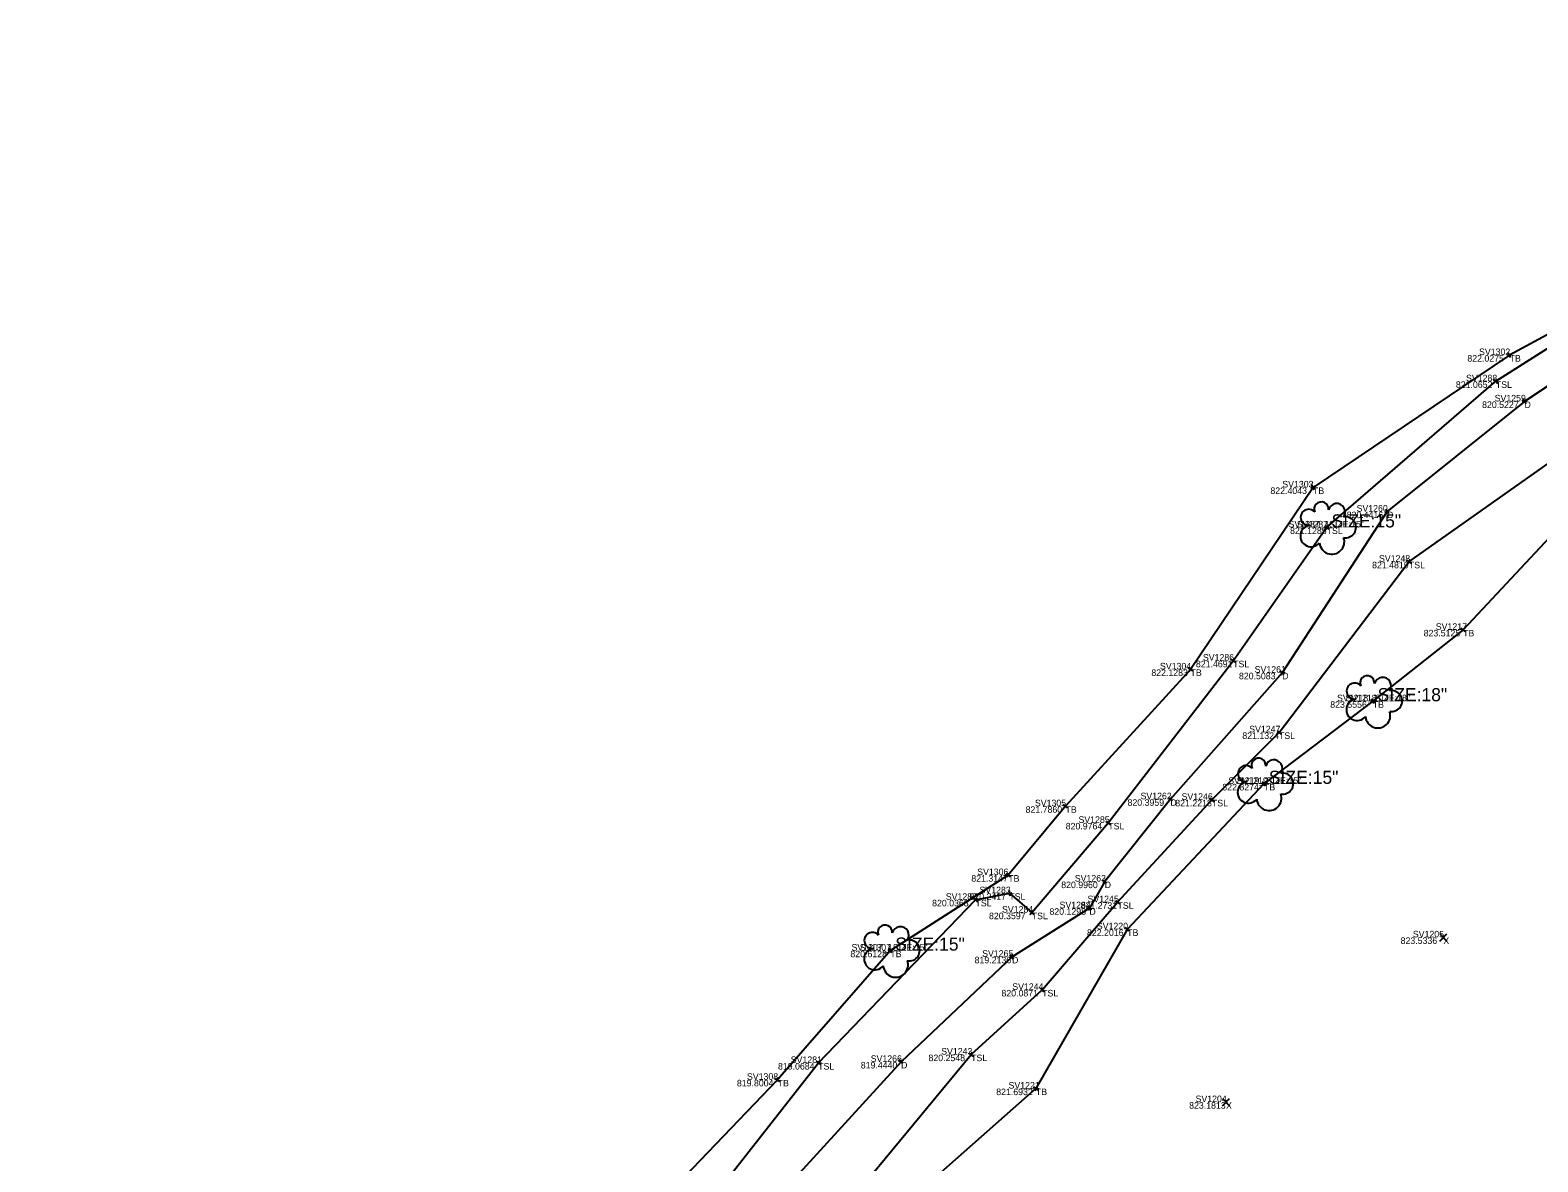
# Model space of a CAD drawing. Extents: x 1715717 to 1717046, y 393954 to 396000.
# Drawn here: x 1716108.5 to 1716246.6, y 395120 to 395223.5 of the extents above; entities that cross this region are included whole.
import ezdxf

# ---------------------------------------------------------------- set-up
doc = ezdxf.new("R2010")
doc.units = 0
for name, color, linetype in [('DR_X_Ditch', 7, 'Continuous'), ('SV_X_Random_Point', 7, 'Continuous'), ('SV_X_Shot_Marker', 7, 'Continuous'), ('SV_X_Text_Comment', 7, 'Continuous'), ('SV_X_Text_Description', 7, 'Continuous'), ('SV_X_Text_Elevation', 7, 'Continuous'), ('SV_X_Text_Name', 7, 'Continuous'), ('SV_X_Toe_of_Slope', 7, 'Continuous'), ('SV_X_Top_of_Bank', 7, 'Continuous'), ('VG_X_Cells', 7, 'Continuous'), ('VG_X_Text', 7, 'Continuous')]:
    doc.layers.add(name, color=color, linetype=linetype)

msp = doc.modelspace()

# ---------------------------------------------------------------- linework, layer by layer
at = {"layer": 'DR_X_Ditch'}
msp.add_lwpolyline([(1716335.63, 395216.63), (1716321.79, 395207.45), (1716304.12, 395202.22), (1716289.35, 395199.62), (1716275.64, 395201.72), (1716256.67, 395197.05), (1716245.34, 395189.54), (1716232.76, 395179.46), (1716223.16, 395164.72), (1716212.92, 395153.14), (1716206.91, 395145.61), (1716205.51, 395143.17), (1716198.43, 395138.73), (1716188.27, 395129.11), (1716177.95, 395117.82), (1716162.4, 395107.22), (1716147.65, 395097.56), (1716133.7, 395088.47), (1716126.82, 395081.72), (1716119.68, 395070.3), (1716114.27, 395069.53), (1716111.44, 395068.21)], dxfattribs=at)
at = {"layer": 'SV_X_Random_Point'}
for p, q in [((1716237.58, 395140.17), (1716238.24, 395140.84)), ((1716237.58, 395140.84), (1716238.24, 395140.17)), ((1716217.68, 395125.1), (1716218.35, 395125.77)), ((1716217.68, 395125.77), (1716218.35, 395125.1))]:
    msp.add_line(p, q, dxfattribs=at)
at = {"layer": 'SV_X_Shot_Marker'}
for p, q in [((1716244.2, 395193.9), (1716243.76, 395193.66)), ((1716244.1, 395193.56), (1716243.86, 395194)), ((1716243.98, 395193.78), (1716243.98, 395193.78)), ((1716242.53, 395191.22), (1716242.91, 395191.54)), ((1716242.56, 395191.57), (1716242.89, 395191.19)), ((1716242.72, 395191.38), (1716242.72, 395191.38)), ((1716245.55, 395189.68), (1716245.13, 395189.4)), ((1716245.48, 395189.33), (1716245.2, 395189.75)), ((1716245.34, 395189.54), (1716245.34, 395189.54)), ((1716226.19, 395181.81), (1716225.77, 395181.53)), ((1716226.12, 395181.46), (1716225.84, 395181.87)), ((1716225.98, 395181.67), (1716225.98, 395181.67)), ((1716232.96, 395179.61), (1716232.57, 395179.3)), ((1716232.92, 395179.26), (1716232.61, 395179.65)), ((1716232.76, 395179.46), (1716232.76, 395179.46)), ((1716227.03, 395178.15), (1716227.44, 395177.86)), ((1716227.09, 395177.8), (1716227.38, 395178.21)), ((1716227.23, 395178.01), (1716227.23, 395178.01)), ((1716234.56, 395175.02), (1716234.96, 395174.72)), ((1716234.61, 395174.67), (1716234.92, 395175.07)), ((1716234.76, 395174.87), (1716234.76, 395174.87)), ((1716239.9, 395168.47), (1716239.53, 395168.81)), ((1716239.89, 395168.82), (1716239.55, 395168.46)), ((1716239.72, 395168.64), (1716239.72, 395168.64)), ((1716214.98, 395164.88), (1716214.56, 395165.16)), ((1716214.91, 395165.23), (1716214.63, 395164.82)), ((1716214.77, 395165.02), (1716214.77, 395165.02)), ((1716218.47, 395165.97), (1716218.87, 395165.66)), ((1716218.52, 395165.62), (1716218.82, 395166.02)), ((1716218.67, 395165.82), (1716218.67, 395165.82)), ((1716223.37, 395164.58), (1716222.95, 395164.85)), ((1716223.3, 395164.93), (1716223.02, 395164.51)), ((1716223.16, 395164.72), (1716223.16, 395164.72)), ((1716231.64, 395162.26), (1716231.25, 395161.95)), ((1716231.6, 395161.91), (1716231.29, 395162.3)), ((1716231.45, 395162.11), (1716231.45, 395162.11)), ((1716222.7, 395159.44), (1716223.05, 395159.09)), ((1716222.7, 395159.09), (1716223.05, 395159.44)), ((1716222.87, 395159.26), (1716222.87, 395159.26)), ((1716221.69, 395154.71), (1716221.29, 395154.4)), ((1716221.64, 395154.35), (1716221.34, 395154.75)), ((1716221.49, 395154.55), (1716221.49, 395154.55)), ((1716203.51, 395152.33), (1716203.14, 395152.67)), ((1716203.49, 395152.68), (1716203.15, 395152.31)), ((1716203.32, 395152.5), (1716203.32, 395152.5)), ((1716213.11, 395152.97), (1716212.74, 395153.3)), ((1716213.09, 395153.32), (1716212.76, 395152.95)), ((1716212.92, 395153.14), (1716212.92, 395153.14)), ((1716216.54, 395153.26), (1716216.91, 395152.92)), ((1716216.56, 395152.91), (1716216.89, 395153.28)), ((1716216.73, 395153.09), (1716216.73, 395153.09)), ((1716207.05, 395151.14), (1716207.43, 395150.81)), ((1716207.08, 395150.79), (1716207.4, 395151.17)), ((1716207.24, 395150.98), (1716207.24, 395150.98)), ((1716198.28, 395146.04), (1716197.89, 395146.36)), ((1716198.24, 395146.39), (1716197.92, 395146)), ((1716198.08, 395146.2), (1716198.08, 395146.2)), ((1716207.11, 395145.46), (1716206.71, 395145.77)), ((1716207.07, 395145.81), (1716206.75, 395145.42)), ((1716206.91, 395145.61), (1716206.91, 395145.61)), ((1716194.9, 395144.11), (1716195.26, 395143.76)), ((1716194.91, 395143.76), (1716195.26, 395144.12)), ((1716197.94, 395144.5), (1716198.43, 395144.59)), ((1716198.13, 395144.79), (1716198.23, 395144.3)), ((1716198.18, 395144.54), (1716198.18, 395144.54)), ((1716195.08, 395143.94), (1716195.08, 395143.94)), ((1716200.04, 395142.93), (1716200.42, 395142.6)), ((1716200.4, 395142.96), (1716200.07, 395142.58)), ((1716200.23, 395142.77), (1716200.23, 395142.77)), ((1716205.73, 395143.04), (1716205.3, 395143.29)), ((1716205.64, 395143.38), (1716205.39, 395142.95)), ((1716205.51, 395143.17), (1716205.51, 395143.17)), ((1716207.89, 395143.88), (1716208.27, 395143.56)), ((1716207.91, 395143.53), (1716208.24, 395143.91)), ((1716208.08, 395143.72), (1716208.08, 395143.72)), ((1716209.15, 395141.06), (1716208.78, 395141.41)), ((1716209.14, 395141.42), (1716208.8, 395141.05)), ((1716208.97, 395141.24), (1716208.97, 395141.24)), ((1716187.5, 395139.43), (1716187.08, 395139.16)), ((1716187.43, 395139.08), (1716187.16, 395139.5)), ((1716187.29, 395139.29), (1716187.29, 395139.29)), ((1716198.64, 395138.86), (1716198.21, 395138.6)), ((1716198.56, 395138.52), (1716198.29, 395138.94)), ((1716198.43, 395138.73), (1716198.43, 395138.73)), ((1716201, 395135.53), (1716201.37, 395135.87)), ((1716201.02, 395135.88), (1716201.35, 395135.51)), ((1716201.18, 395135.7), (1716201.18, 395135.7)), ((1716180.49, 395129.17), (1716180.88, 395128.86)), ((1716180.53, 395128.81), (1716180.84, 395129.21)), ((1716180.68, 395129.01), (1716180.68, 395129.01)), ((1716188.45, 395129.28), (1716188.09, 395128.93)), ((1716188.44, 395128.93), (1716188.1, 395129.29)), ((1716188.27, 395129.11), (1716188.27, 395129.11)), ((1716194.48, 395129.94), (1716194.87, 395129.62)), ((1716194.52, 395129.59), (1716194.84, 395129.97)), ((1716194.68, 395129.78), (1716194.68, 395129.78)), ((1716177.16, 395127.3), (1716176.78, 395127.63)), ((1716177.13, 395127.65), (1716176.8, 395127.28)), ((1716176.97, 395127.47), (1716176.97, 395127.47)), ((1716200.83, 395126.54), (1716200.39, 395126.79)), ((1716200.73, 395126.88), (1716200.49, 395126.45)), ((1716200.61, 395126.67), (1716200.61, 395126.67))]:
    msp.add_line(p, q, dxfattribs=at)
at = {"layer": 'SV_X_Toe_of_Slope'}
for points in [[(1716109.35, 395070.75), (1716114.74, 395071.83), (1716125.09, 395083.41), (1716138.53, 395095.72), (1716153.68, 395103.74), (1716168.61, 395113.58), (1716180.68, 395129.01), (1716195.08, 395143.94), (1716198.18, 395144.54), (1716200.23, 395142.77), (1716207.24, 395150.98), (1716218.67, 395165.82), (1716227.23, 395178.01), (1716242.72, 395191.38), (1716255.46, 395199.49), (1716270.61, 395203.99), (1716279.96, 395206.87), (1716290.84, 395202.03), (1716301.4, 395204.23), (1716321.04, 395209.69), (1716337.66, 395219.83)], [(1716112.34, 395065.13), (1716118.47, 395067.07), (1716121.66, 395068.34), (1716133.3, 395082.57), (1716150.43, 395097.08), (1716166.72, 395105.82), (1716185.49, 395118.69), (1716194.68, 395129.78), (1716201.18, 395135.7), (1716208.08, 395143.72), (1716216.73, 395153.09), (1716222.87, 395159.26), (1716234.76, 395174.87), (1716259.96, 395192.65), (1716284.08, 395195.1), (1716296.15, 395195.51), (1716316.17, 395201.17)]]:
    msp.add_lwpolyline(points, dxfattribs=at)
at = {"layer": 'SV_X_Top_of_Bank'}
for points in [[(1716335.25, 395223.51), (1716320.65, 395211.92), (1716306.73, 395206.83), (1716291.71, 395204.04), (1716278.01, 395208.19), (1716261.04, 395202.98), (1716243.98, 395193.78), (1716225.98, 395181.67), (1716214.77, 395165.02), (1716203.32, 395152.5), (1716198.08, 395146.2), (1716187.29, 395139.29), (1716176.97, 395127.47), (1716165.6, 395115.64), (1716155.48, 395107.53), (1716139.02, 395097.43), (1716122.72, 395086.97), (1716119.12, 395087.96), (1716111.41, 395078.01), (1716106.46, 395075.28), (1716105.76, 395069.24)], [(1716344.96, 395206.21), (1716305.52, 395190.87), (1716290.29, 395192.03), (1716282.16, 395193.91), (1716268.06, 395190.32), (1716251.98, 395181.76), (1716239.72, 395168.64), (1716231.45, 395162.11), (1716221.49, 395154.55), (1716208.97, 395141.24), (1716200.61, 395126.67), (1716184.53, 395112.45), (1716168.23, 395100.64), (1716149.61, 395090.75), (1716137.18, 395077), (1716131.44, 395068.87), (1716127.31, 395065.53), (1716124.51, 395063.75), (1716122.94, 395061.89), (1716115.38, 395061.63), (1716111.81, 395062.74)]]:
    msp.add_lwpolyline(points, dxfattribs=at)
at = {"layer": 'VG_X_Cells'}
for centre in [(1716227.23, 395178.01), (1716231.45, 395162.11), (1716221.49, 395154.55), (1716187.29, 395139.29)]:
    msp.add_circle(centre, 0.12, dxfattribs=at)
for centre, radius, start, end in [((1716226.74, 395179.69), 0.658, 354.0047, 205.9741), ((1716228.15, 395179.42), 0.776, 323.83, 165.0376), ((1716225.58, 395178.94), 0.735, 39.0625, 279.5412), ((1716228.96, 395178.02), 0.957, 259.1453, 101.4596), ((1716225.81, 395177.23), 0.987, 96.1722, 320.5737), ((1716227.71, 395176.7), 1.14, 184.9476, 19.4572), ((1716229.79, 395163.04), 0.735, 39.0625, 279.5412), ((1716230.95, 395163.79), 0.658, 354.0047, 205.9741), ((1716232.36, 395163.52), 0.776, 323.83, 165.0376), ((1716230.02, 395161.33), 0.987, 96.1722, 320.5737), ((1716233.18, 395162.13), 0.957, 259.1453, 101.4596), ((1716231.92, 395160.8), 1.14, 184.9476, 19.4572), ((1716221, 395156.24), 0.658, 354.0047, 205.9741), ((1716222.4, 395155.97), 0.776, 323.83, 165.0376), ((1716219.84, 395155.49), 0.735, 39.0625, 279.5412), ((1716223.22, 395154.57), 0.957, 259.1453, 101.4596), ((1716220.06, 395153.78), 0.987, 96.1722, 320.5737), ((1716221.96, 395153.25), 1.14, 184.9476, 19.4572), ((1716186.8, 395140.98), 0.658, 354.0047, 205.9741), ((1716188.21, 395140.71), 0.776, 323.83, 165.0376), ((1716185.64, 395140.22), 0.735, 39.0625, 279.5412), ((1716189.02, 395139.31), 0.957, 259.1453, 101.4596), ((1716185.87, 395138.52), 0.987, 96.1722, 320.5737), ((1716187.77, 395137.99), 1.14, 184.9476, 19.4572)]:
    msp.add_arc(centre, radius, start, end, dxfattribs=at)

# ---------------------------------------------------------------- texts
at = {"layer": 'SV_X_Text_Comment'}
for s, p in [('TB', (1716243.98, 395193.18)), ('TSL', (1716242.72, 395190.78)), ('D', (1716245.34, 395188.94)), ('TB', (1716225.98, 395181.07)), ('D', (1716232.76, 395178.86)), ('TSL', (1716227.23, 395177.41)), ('T', (1716227.23, 395177.41)), ('TSL', (1716234.76, 395174.27)), ('TB', (1716239.72, 395168.04)), ('TB', (1716214.77, 395164.42)), ('TSL', (1716218.67, 395165.22)), ('D', (1716223.16, 395164.12)), ('TB', (1716231.45, 395161.51)), ('T', (1716231.45, 395161.51)), ('TSL', (1716222.87, 395158.66)), ('TB', (1716221.49, 395153.95)), ('T', (1716221.49, 395153.95)), ('TB', (1716203.32, 395151.9)), ('D', (1716212.92, 395152.54)), ('TSL', (1716216.73, 395152.49)), ('TSL', (1716207.24, 395150.38)), ('TB', (1716198.08, 395145.6)), ('D', (1716206.91, 395145.01)), ('TSL', (1716198.18, 395143.94)), ('TSL', (1716195.08, 395143.34)), ('TSL', (1716200.23, 395142.17)), ('D', (1716205.51, 395142.57)), ('TSL', (1716208.08, 395143.12)), ('TB', (1716208.97, 395140.64)), ('X', (1716237.91, 395139.9)), ('TB', (1716187.29, 395138.69)), ('T', (1716187.29, 395138.69)), ('D', (1716198.43, 395138.13)), ('TSL', (1716201.18, 395135.1)), ('TSL', (1716180.68, 395128.41)), ('D', (1716188.27, 395128.51)), ('TSL', (1716194.68, 395129.18)), ('TB', (1716176.97, 395126.87)), ('TB', (1716200.61, 395126.07)), ('X', (1716218.02, 395124.83))]:
    msp.add_text(s, height=0.6, dxfattribs=at).set_placement(p)
at = {"layer": 'SV_X_Text_Description'}
for s, p in [(' SIZE:15" ', (1716227.23, 395178.01)), (' SIZE:18" ', (1716231.45, 395162.11)), (' SIZE:15" ', (1716221.49, 395154.55)), (' SIZE:15" ', (1716187.29, 395139.29))]:
    msp.add_text(s, height=0.6, dxfattribs=at).set_placement(p)
at = {"layer": 'SV_X_Text_Elevation'}
for s, p in [('822.0275', (1716240.11, 395193.18)), ('821.0652', (1716239.06, 395190.78)), ('820.5227', (1716241.46, 395188.94)), ('822.4043', (1716222.08, 395181.07)), ('820.4416', (1716229.06, 395178.86)), ('821.1285', (1716223.88, 395177.41)), ('821.1285', (1716223.88, 395177.41)), ('821.4819', (1716231.39, 395174.27)), ('823.5125', (1716236.11, 395168.04)), ('822.1283', (1716211.18, 395164.42)), ('821.4691', (1716215.26, 395165.22)), ('820.5083', (1716219.2, 395164.12)), ('823.5556', (1716227.56, 395161.51)), ('823.5556', (1716227.56, 395161.51)), ('821.1324', (1716219.51, 395158.66)), ('822.8274', (1716217.68, 395153.95)), ('822.8274', (1716217.68, 395153.95)), ('821.7860', (1716199.67, 395151.9)), ('820.3959', (1716209, 395152.54)), ('821.2218', (1716213.37, 395152.49)), ('820.9764', (1716203.34, 395150.38)), ('821.3147', (1716194.7, 395145.6)), ('820.9960', (1716202.93, 395145.01)), ('820.2417', (1716194.53, 395143.94)), ('820.0368', (1716191.11, 395143.34)), ('820.3597', (1716196.32, 395142.17)), ('820.1298', (1716201.85, 395142.57)), ('821.2731', (1716204.7, 395143.12)), ('822.2016', (1716205.29, 395140.64)), ('823.5336', (1716234, 395139.9)), ('820.6128', (1716183.63, 395138.69)), ('820.6128', (1716183.63, 395138.69)), ('819.2136', (1716195, 395138.13)), ('820.0871', (1716197.46, 395135.1)), ('819.0684', (1716177, 395128.41)), ('819.4440', (1716184.58, 395128.51)), ('820.2548', (1716190.78, 395129.18)), ('819.8004', (1716173.24, 395126.87)), ('821.6932', (1716196.98, 395126.07)), ('823.1813', (1716214.64, 395124.83))]:
    msp.add_text(s, height=0.6, dxfattribs=at).set_placement(p)
at = {"layer": 'SV_X_Text_Name'}
for s, p in [('SV1302', (1716241.18, 395193.78)), ('SV1288', (1716239.99, 395191.38)), ('SV1259', (1716242.61, 395189.54)), ('SV1303', (1716223.17, 395181.67)), ('SV1260', (1716229.97, 395179.46)), ('SV1287_1', (1716223.74, 395178.01)), ('SV1287', (1716224.5, 395178.01)), ('SV1248', (1716232.02, 395174.87)), ('SV1217', (1716237.22, 395168.64)), ('SV1286', (1716215.9, 395165.82)), ('SV1304', (1716211.97, 395165.02)), ('SV1261', (1716220.64, 395164.72)), ('SV1218_1', (1716228.18, 395162.11)), ('SV1218', (1716228.95, 395162.11)), ('SV1247', (1716220.14, 395159.26)), ('SV1219_1', (1716218.22, 395154.55)), ('SV1219', (1716218.99, 395154.55)), ('SV1262', (1716210.19, 395153.14)), ('SV1246', (1716213.95, 395153.09)), ('SV1305', (1716200.52, 395152.5)), ('SV1285', (1716204.51, 395150.98)), ('SV1306', (1716195.24, 395146.2)), ('SV1263', (1716204.17, 395145.61)), ('SV1282', (1716192.36, 395143.94)), ('SV1283', (1716195.45, 395144.54)), ('SV1245', (1716205.34, 395143.72)), ('SV1284', (1716197.51, 395142.77)), ('SV1264', (1716202.78, 395143.17)), ('SV1220', (1716206.19, 395141.24)), ('SV1307_1', (1716183.73, 395139.29)), ('SV1307', (1716184.49, 395139.29)), ('SV1205', (1716235.12, 395140.5)), ('SV1265', (1716195.69, 395138.73)), ('SV1244', (1716198.45, 395135.7)), ('SV1243', (1716191.94, 395129.78)), ('SV1281', (1716178.17, 395129.01)), ('SV1266', (1716185.49, 395129.11)), ('SV1308', (1716174.16, 395127.47)), ('SV1221', (1716198.11, 395126.67)), ('SV1204', (1716215.23, 395125.43))]:
    msp.add_text(s, height=0.6, dxfattribs=at).set_placement(p)
at = {"layer": 'VG_X_Text'}
for s, p in [(' SIZE:15" ', (1716227.23, 395178.01)), (' SIZE:18" ', (1716231.45, 395162.11)), (' SIZE:15" ', (1716221.49, 395154.55)), (' SIZE:15" ', (1716187.29, 395139.29))]:
    msp.add_text(s, height=1.2, dxfattribs=at).set_placement(p)

doc.saveas('drawing.dxf')
